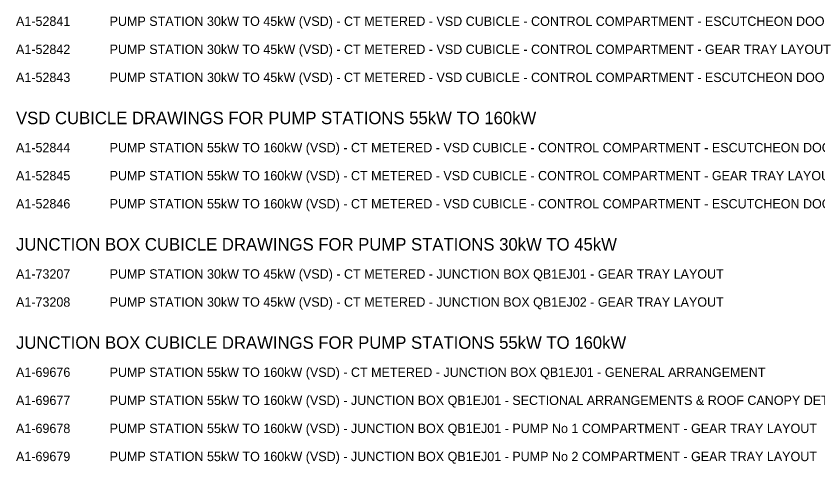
# Model space of a CAD drawing. Extents: x 0 to 841, y 0 to 594.
# Drawn here: x 440 to 697, y 148.6 to 292.2 of the extents above; entities that cross this region are included whole.
import ezdxf

# ---------------------------------------------------------------- set-up
doc = ezdxf.new("R2010")
doc.units = 0
doc.layers.add('Level 1', color=7, linetype='Continuous')

msp = doc.modelspace()

# ---------------------------------------------------------------- texts
at = {"layer": 'Level 1'}
for s, height, p in [('A1-52841', 3, (440, 289)), ('PUMP STATION 30kW TO 45kW (VSD) - CT METERED - VSD CUBICLE - CONTROL COMPARTMENT - ESCUTCHEON DOOR LAYOUT', 3, (470, 288.999)), ('A1-52842', 3, (440, 280)), ('PUMP STATION 30kW TO 45kW (VSD) - CT METERED - VSD CUBICLE - CONTROL COMPARTMENT - GEAR TRAY LAYOUT', 3, (470, 280)), ('A1-52843', 3, (440, 271)), ('PUMP STATION 30kW TO 45kW (VSD) - CT METERED - VSD CUBICLE - CONTROL COMPARTMENT - ESCUTCHEON DOOR CUTOUT DETAILS', 3, (470, 271)), ('VSD CUBICLE DRAWINGS FOR PUMP STATIONS 55kW TO 160kW', 4, (440, 257.5)), ('A1-52844', 3, (440, 248.5)), ('PUMP STATION 55kW TO 160kW (VSD) - CT METERED - VSD CUBICLE - CONTROL COMPARTMENT - ESCUTCHEON DOOR LAYOUT', 3, (470, 248.499)), ('A1-52845', 3, (440, 239.5)), ('PUMP STATION 55kW TO 160kW (VSD) - CT METERED - VSD CUBICLE - CONTROL COMPARTMENT - GEAR TRAY LAYOUT', 3, (470, 239.5)), ('A1-52846', 3, (440, 230.5)), ('PUMP STATION 55kW TO 160kW (VSD) - CT METERED - VSD CUBICLE - CONTROL COMPARTMENT - ESCUTCHEON DOOR CUTOUT DETAILS', 3, (470, 230.5)), ('JUNCTION BOX CUBICLE DRAWINGS FOR PUMP STATIONS 30kW TO 45kW', 4, (440, 217)), ('A1-73207', 3, (440, 208)), ('PUMP STATION 30kW TO 45kW (VSD) - CT METERED - JUNCTION BOX QB1EJ01 - GEAR TRAY LAYOUT', 3, (470, 207.999)), ('A1-73208', 3, (440, 199)), ('PUMP STATION 30kW TO 45kW (VSD) - CT METERED - JUNCTION BOX QB1EJ02 - GEAR TRAY LAYOUT', 3, (470, 199)), ('JUNCTION BOX CUBICLE DRAWINGS FOR PUMP STATIONS 55kW TO 160kW', 4, (440, 185.5)), ('A1-69676', 3, (440, 176.5)), ('PUMP STATION 55kW TO 160kW (VSD) - CT METERED - JUNCTION BOX QB1EJ01 - GENERAL ARRANGEMENT', 3, (470, 176.499)), ('A1-69677', 3, (440, 167.5)), ('PUMP STATION 55kW TO 160kW (VSD) - JUNCTION BOX QB1EJ01 - SECTIONAL ARRANGEMENTS & ROOF CANOPY DETAILS', 3, (470, 167.5)), ('A1-69678', 3, (440, 158.5)), ('PUMP STATION 55kW TO 160kW (VSD) - JUNCTION BOX QB1EJ01 - PUMP No 1 COMPARTMENT - GEAR TRAY LAYOUT', 3, (470, 158.5)), ('A1-69679', 3, (440, 149.5)), ('PUMP STATION 55kW TO 160kW (VSD) - JUNCTION BOX QB1EJ01 - PUMP No 2 COMPARTMENT - GEAR TRAY LAYOUT', 3, (470, 149.5))]:
    msp.add_text(s, height=height, dxfattribs=at).set_placement(p)

doc.saveas('drawing.dxf')
